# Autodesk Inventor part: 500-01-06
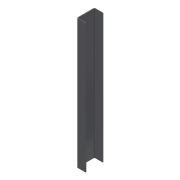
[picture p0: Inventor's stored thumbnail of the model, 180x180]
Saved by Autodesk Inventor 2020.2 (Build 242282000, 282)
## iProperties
Created: 2015-10
Part Number: 500-01-06
Material: Stal
Document SubType Name: Konstrukcja blachowa
Designer: F.Stasiak
Density: 7.85 g/cm^3
Sheet Metal Rule: Domyślny_mm
Appearance: Płyta
Description: Szyna
Manager: www.cadconsulting.pl
Company: Fabian Stasiak CAD Consulting
Author: F.Stasiak
Subject: Zbiór ćwiczeń. Autodesk Inventor 2020. Kurs podstawowy
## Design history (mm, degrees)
node "Kołnierz z profilu1"
  sketch "Szkic1"
    geometry: L1 (60, -60)-(0, -60); L2 (0, -60)-(0, 60); L3 (0, 60)-(60, 60); 2 further points
    constraints: 6 end point, 2 perpendicular, 1 coincident, 1 horizontal, 1 midpoint, 1 parallel
    dimensions: "d0" = 120 distance of L1.end L2.end; "d1" = 60 distance of L1.start L1.end
node "Bryła1"
feature "Płyta1" dims "d2" = 4.5 (= SzerokośćGięciaPodcięcia), "d3" = 2.25 (= GłębokośćGięciaPodcięcia), "d4" = 9 (= MinimalnaPozostałość), "d5" = 4.5 (= PromieńGięcia), "d6" = 870, "d7" = 4.5 (= PromieńGięcia), "d8" = 3.5, "d9" = 18 (= RozmiarPodcięciaNarożnika), "d10" = 4.5 (= Wielk_odstępu), "d11" = 4.5 (= Rozmiar_promienia_Jacobiego), "d12" = 4.5 (= Grubość), "OdstępPołączenia" = 0.01
feature "Gięcie1" dims "d2" = 4.5 (= SzerokośćGięciaPodcięcia), "d3" = 2.25 (= GłębokośćGięciaPodcięcia), "d4" = 9 (= MinimalnaPozostałość), "d5" = 4.5 (= PromieńGięcia), "d7" = 4.5 (= PromieńGięcia), "d8" = 3.5, "d12" = 4.5 (= Grubość), "OdstępPołączenia" = 0.01
feature "Narożnik1" dims "d8" = 3.5, "d9" = 18 (= RozmiarPodcięciaNarożnika), "d10" = 4.5 (= Wielk_odstępu), "d11" = 4.5 (= Rozmiar_promienia_Jacobiego)
other parameters: "Grubość" = 4.5, "WspółczynnikK" = 4.4, "PromieńGięcia" = 4.5 (= Grubość), "SzerokośćGięciaPodcięcia" = 4.5 (= Grubość), "GłębokośćGięciaPodcięcia" = 2.25 (= 0.5 x Grubość), "RozmiarPodcięciaNarożnika" = 18 (= 4 x Grubość), "MinimalnaPozostałość" = 9 (= 2 x Grubość), "PromieńPrzejścia" = 4.5 (= PromieńGięcia), "Rozmiar_promienia_Jacobiego" = 4.5 (= PromieńGięcia), "Wielk_odstępu" = 4.5 (= Grubość)
